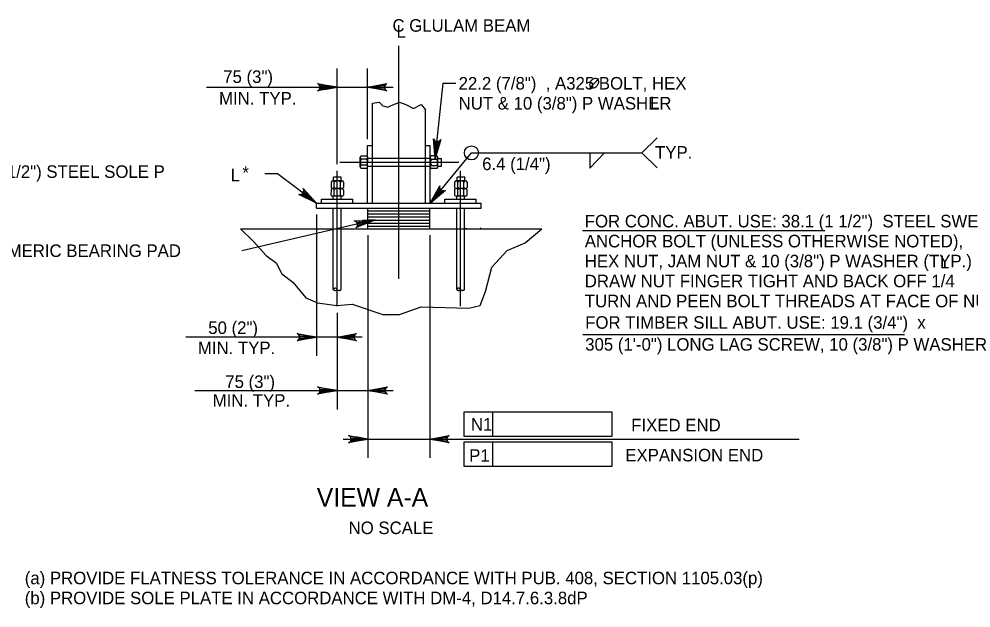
# Model space of a CAD drawing. Extents: x 638263 to 640360, y 293683 to 298655.
# Drawn here: x 638729.9 to 638957.6, y 295056.6 to 295197.6 of the extents above; entities that cross this region are included whole.
import ezdxf

# ---------------------------------------------------------------- set-up
doc = ezdxf.new("R2010")
doc.units = 0
doc.layers.add('3', color=7, linetype='Continuous')
doc.layers.add('4', color=7, linetype='Continuous')

msp = doc.modelspace()

# ---------------------------------------------------------------- linework, layer by layer
at = {"layer": '3'}
for p, q in [((638820.73, 295135.39), (638820.73, 295191.14)), ((638814.39, 295153.48), (638814.39, 295177.4)), ((638827.06, 295153.48), (638827.06, 295175.87)), ((638813.21, 295167.26), (638814.39, 295167.26)), ((638813.21, 295153.48), (638813.21, 295167.26)), ((638827.06, 295167.26), (638828.24, 295167.26)), ((638828.24, 295153.48), (638828.24, 295167.26)), ((638811.72, 295164.84), (638813, 295164.84)), ((638829.79, 295164.79), (638828.5, 295164.79)), ((638806.6, 295163.33), (638835.04, 295163.33)), ((638811.44, 295162.19), (638811.45, 295164.47)), ((638813, 295164.06), (638811.71, 295164.06)), ((638812.99, 295162.56), (638811.71, 295162.56)), ((638813.26, 295162.18), (638813.27, 295164.46)), ((638813.26, 295162.38), (638828.23, 295162.38)), ((638813.27, 295164.25), (638828.24, 295164.25)), ((638828.23, 295162.15), (638828.24, 295164.42)), ((638828.5, 295164.02), (638829.79, 295164.02)), ((638828.5, 295162.52), (638829.79, 295162.52)), ((638830.05, 295162.14), (638830.05, 295164.42)), ((638830.05, 295164.19), (638830.96, 295164.18)), ((638830.05, 295162.34), (638830.95, 295162.34)), ((638830.95, 295162.34), (638830.96, 295164.18)), ((638805.96, 295128.82), (638805.96, 295161.26)), ((638811.71, 295161.84), (638812.99, 295161.84)), ((638829.78, 295161.79), (638828.5, 295161.8)), ((638835.49, 295128.82), (638835.49, 295161.26)), ((638804.5, 295158.54), (638804.5, 295157.26)), ((638807.15, 295158.8), (638804.88, 295158.81)), ((638805.1, 295158.81), (638805.11, 295159.71)), ((638806.95, 295159.71), (638805.11, 295159.71)), ((638805.28, 295157.26), (638805.28, 295158.54)), ((638806.77, 295157.25), (638806.78, 295158.54)), ((638806.95, 295158.8), (638806.95, 295159.71)), ((638807.5, 295158.54), (638807.5, 295157.25)), ((638834.03, 295158.54), (638834.03, 295157.26)), ((638836.68, 295158.8), (638834.4, 295158.81)), ((638836.48, 295159.71), (638834.63, 295159.71)), ((638834.63, 295158.81), (638834.63, 295159.71)), ((638834.8, 295157.26), (638834.8, 295158.54)), ((638836.3, 295157.25), (638836.3, 295158.54)), ((638836.48, 295158.8), (638836.48, 295159.71)), ((638837.03, 295158.54), (638837.03, 295157.25)), ((638804.5, 295156.73), (638804.49, 295155.44)), ((638807.15, 295156.99), (638804.87, 295156.99)), ((638805.27, 295155.44), (638805.27, 295156.73)), ((638806.77, 295155.44), (638806.77, 295156.72)), ((638807.5, 295156.72), (638807.49, 295155.44)), ((638834.03, 295156.73), (638834.02, 295155.44)), ((638836.68, 295156.99), (638834.4, 295156.99)), ((638834.8, 295155.44), (638834.8, 295156.73)), ((638836.3, 295155.44), (638836.3, 295156.72)), ((638837.02, 295156.72), (638837.02, 295155.44)), ((638801.04, 295152.3), (638801.04, 295153.48)), ((638801.04, 295153.48), (638840.41, 295153.48)), ((638802.22, 295153.48), (638802.22, 295154.47)), ((638802.22, 295154.47), (638809.7, 295154.47)), ((638807.14, 295155.17), (638804.87, 295155.18)), ((638805.04, 295154.47), (638805.04, 295155.18)), ((638806.91, 295154.47), (638806.91, 295155.17)), ((638809.7, 295153.48), (638809.7, 295154.47)), ((638831.75, 295154.47), (638839.23, 295154.47)), ((638831.75, 295153.48), (638831.75, 295154.47)), ((638836.67, 295155.17), (638834.4, 295155.18)), ((638834.57, 295154.47), (638834.57, 295155.18)), ((638836.43, 295154.47), (638836.43, 295155.17)), ((638839.23, 295153.48), (638839.23, 295154.47)), ((638840.41, 295152.3), (638840.41, 295153.48)), ((638801.04, 295152.3), (638840.41, 295152.3)), ((638805.04, 295147.38), (638805.04, 295152.3)), ((638806.91, 295147.38), (638806.91, 295152.3)), ((638813.34, 295147.38), (638813.34, 295152.3)), ((638813.34, 295151.67), (638820.73, 295151.67)), ((638813.34, 295150.93), (638820.73, 295150.93)), ((638820.73, 295151.67), (638828.11, 295151.67)), ((638820.73, 295150.93), (638828.11, 295150.93)), ((638828.11, 295147.38), (638828.11, 295152.3)), ((638834.57, 295147.38), (638834.57, 295152.3)), ((638836.43, 295147.38), (638836.43, 295152.3)), ((638813.34, 295150.19), (638820.73, 295150.19)), ((638813.34, 295149.46), (638820.73, 295149.46)), ((638813.34, 295148.72), (638820.73, 295148.72)), ((638820.73, 295150.19), (638828.11, 295150.19)), ((638820.73, 295149.46), (638828.11, 295149.46)), ((638820.73, 295148.72), (638828.11, 295148.72)), ((638782.88, 295147.38), (638854.89, 295147.38)), ((638805.04, 295132.86), (638805.04, 295147.38)), ((638806.91, 295132.85), (638806.91, 295147.38)), ((638813.34, 295147.98), (638820.73, 295147.98)), ((638820.73, 295147.98), (638828.11, 295147.98)), ((638834.57, 295132.86), (638834.57, 295147.38)), ((638836.43, 295132.85), (638836.43, 295147.38))]:
    msp.add_line(p, q, dxfattribs=at)
for points in [[(638814.39, 295177.4), (638815.98, 295177.71), (638816.9, 295176.79), (638818.12, 295176.48), (638818.73, 295176.79), (638820.88, 295177.71), (638822.41, 295177.1), (638824.25, 295176.18), (638826.09, 295177.1), (638827.06, 295175.87)], [(638801.04, 295153.49), (638796.79, 295155.59), (638797.23, 295155.58), (638797.56, 295155.72), (638797.8, 295155.93), (638797.94, 295156.21), (638797.98, 295156.57), (638797.84, 295156.99), (638801.04, 295153.49), (638797.98, 295156.57), (638797.94, 295156.21), (638801.04, 295153.49), (638797.8, 295155.93), (638797.56, 295155.72), (638801.04, 295153.49), (638797.23, 295155.58)], [(638814.77, 295149.46), (638810.43, 295147.55), (638810.72, 295147.87), (638810.83, 295148.22), (638810.82, 295148.53), (638810.69, 295148.83), (638810.44, 295149.09), (638810.03, 295149.25), (638814.77, 295149.46), (638810.44, 295149.09), (638810.69, 295148.83), (638814.77, 295149.46), (638810.82, 295148.53), (638810.83, 295148.22), (638814.77, 295149.46), (638810.72, 295147.87)], [(638782.88, 295147.38), (638785.94, 295144.32), (638789.01, 295140.95), (638791.46, 295139.11), (638792.69, 295136.66), (638795.44, 295134.52), (638798.51, 295130.84), (638801.27, 295129.62), (638805.86, 295129), (638809.54, 295129.31), (638816.9, 295126.86), (638820.88, 295126.86), (638826.09, 295128.7), (638837.43, 295128.39), (638840.19, 295129), (638841.41, 295132.37), (638842.94, 295138.19), (638846.62, 295142.17), (638850.91, 295144.01), (638854.89, 295147.38)]]:
    msp.add_lwpolyline(points, dxfattribs=at)
for centre, radius, start, end in [((638811.87, 295164.45), 0.417, 111.1104, 181.6506), ((638812.85, 295164.45), 0.417, 357.9964, 68.5366), ((638828.65, 295164.41), 0.417, 111.1685, 181.7086), ((638829.64, 295164.4), 0.417, 358.0545, 68.5946), ((638811.82, 295162.2), 0.379, 107.2753, 252.3717), ((638811.87, 295164.45), 0.417, 181.6506, 248.5366), ((638812.64, 295163.31), 1.19, 140.8735, 218.7735), ((638812.07, 295163.31), 1.19, 320.8735, 38.7735), ((638812.88, 295162.2), 0.379, 287.2753, 72.3717), ((638812.85, 295164.45), 0.417, 291.1104, 357.9964), ((638829.43, 295163.27), 1.19, 140.9315, 218.8315), ((638828.61, 295162.16), 0.379, 107.3333, 252.4297), ((638828.65, 295164.41), 0.417, 181.7086, 248.5946), ((638828.86, 295163.27), 1.19, 320.9315, 38.8315), ((638829.67, 295162.16), 0.379, 287.3333, 72.4297), ((638829.64, 295164.4), 0.417, 291.1685, 358.0545), ((638804.89, 295158.39), 0.417, 88.0545, 158.5946), ((638804.89, 295158.39), 0.417, 21.1685, 88.0545), ((638806.02, 295157.61), 1.19, 50.9315, 128.8315), ((638807.14, 295158.43), 0.379, 17.3333, 162.4297), ((638834.42, 295158.39), 0.417, 88.0545, 158.5946), ((638834.42, 295158.39), 0.417, 21.1685, 88.0545), ((638835.55, 295157.61), 1.19, 50.9315, 128.8315), ((638836.66, 295158.43), 0.379, 17.3333, 162.4297), ((638804.88, 295155.59), 0.417, 201.1685, 271.7086), ((638804.89, 295157.41), 0.417, 201.1685, 271.7086), ((638804.88, 295156.58), 0.417, 88.0545, 158.5946), ((638804.88, 295155.59), 0.417, 271.7086, 338.5946), ((638804.88, 295156.58), 0.417, 21.1685, 88.0545), ((638806.03, 295158.18), 1.19, 230.9315, 308.8315), ((638806.02, 295155.8), 1.19, 50.9315, 128.8315), ((638806.02, 295156.37), 1.19, 230.9315, 308.8315), ((638807.13, 295157.37), 0.379, 197.3333, 342.4297), ((638807.13, 295156.61), 0.379, 17.3333, 162.4297), ((638807.13, 295155.55), 0.379, 197.3333, 342.4297), ((638834.41, 295156.58), 0.417, 88.0545, 158.5946), ((638834.41, 295155.59), 0.417, 201.1685, 271.7086), ((638834.41, 295157.41), 0.417, 201.1685, 271.7086), ((638834.41, 295155.59), 0.417, 271.7086, 338.5946), ((638834.41, 295157.41), 0.417, 271.7086, 338.5946), ((638834.41, 295156.58), 0.417, 21.1685, 88.0545), ((638835.55, 295158.18), 1.19, 230.9315, 308.8315), ((638835.55, 295155.8), 1.19, 50.9315, 128.8315), ((638835.55, 295156.37), 1.19, 230.9315, 308.8315), ((638836.66, 295157.37), 0.379, 197.3333, 342.4297), ((638836.66, 295156.61), 0.379, 17.3333, 162.4297), ((638836.66, 295155.55), 0.379, 197.3333, 342.4297), ((638805.17, 295132.86), 0.137, 142.0693, 180), ((638805.17, 295132.86), 0.137, 180, 217.9307), ((638805.33, 295132.74), 0.333, 117.9903, 142.0693), ((638805.33, 295132.98), 0.333, 217.9307, 242.0097), ((638805.43, 295132.54), 0.552, 102.4157, 117.9903), ((638805.43, 295133.17), 0.552, 242.0097, 257.5843), ((638805.5, 295132.24), 0.867, 90, 102.4157), ((638805.5, 295132.24), 0.867, 77.5843, 90), ((638805.57, 295132.54), 0.552, 62.0097, 77.5843), ((638805.57, 295133.17), 0.552, 282.4157, 297.9903), ((638805.67, 295132.74), 0.333, 37.9307, 62.0097), ((638805.67, 295132.98), 0.333, 297.9903, 322.0693), ((638805.82, 295132.86), 0.137, 0, 37.9307), ((638805.82, 295132.86), 0.137, 322.0693, 0), ((638806.1, 295132.85), 0.137, 180, 217.9307), ((638806.25, 295132.97), 0.333, 217.9307, 242.0097), ((638806.36, 295133.16), 0.552, 242.0097, 257.5843), ((638806.49, 295133.16), 0.552, 282.4157, 297.9903), ((638806.59, 295132.97), 0.333, 297.9903, 322.0693), ((638806.75, 295132.85), 0.137, 322.0693, 360), ((638806.75, 295132.85), 0.137, 360, 1.757), ((638834.7, 295132.86), 0.137, 142.0693, 180), ((638834.7, 295132.86), 0.137, 180, 217.9307), ((638834.86, 295132.74), 0.333, 117.9903, 142.0693), ((638834.86, 295132.98), 0.333, 217.9307, 242.0097), ((638834.96, 295132.54), 0.552, 102.4157, 117.9903), ((638834.96, 295133.17), 0.552, 242.0097, 257.5843), ((638835.03, 295132.24), 0.867, 90, 102.4157), ((638835.03, 295132.24), 0.867, 77.5843, 90), ((638835.09, 295132.54), 0.552, 62.0097, 77.5843), ((638835.09, 295133.17), 0.552, 282.4157, 297.9903), ((638835.2, 295132.74), 0.333, 37.9307, 62.0097), ((638835.2, 295132.98), 0.333, 297.9903, 322.0693), ((638835.35, 295132.86), 0.137, 0, 37.9307), ((638835.35, 295132.86), 0.137, 322.0693, 0), ((638835.63, 295132.85), 0.137, 180, 217.9307), ((638835.78, 295132.97), 0.333, 217.9307, 242.0097), ((638835.88, 295133.16), 0.552, 242.0097, 257.5843), ((638836.02, 295133.16), 0.552, 282.4157, 297.9903), ((638836.12, 295132.97), 0.333, 297.9903, 322.0693), ((638836.28, 295132.85), 0.137, 322.0693, 360), ((638836.28, 295132.85), 0.137, 360, 1.757), ((638805.5, 295133.48), 0.867, 257.5843, 270), ((638805.5, 295133.48), 0.867, 270, 282.4157), ((638806.42, 295133.47), 0.867, 257.5843, 270), ((638806.42, 295133.47), 0.867, 270, 282.4157), ((638835.03, 295133.48), 0.867, 257.5843, 270), ((638835.03, 295133.48), 0.867, 270, 282.4157), ((638835.95, 295133.47), 0.867, 257.5843, 270), ((638835.95, 295133.47), 0.867, 270, 282.4157)]:
    msp.add_arc(centre, radius, start, end, dxfattribs=at)
at = {"layer": '4'}
for p, q in [((638805.96, 295162.82), (638805.96, 295185.74)), ((638813.21, 295168.83), (638813.21, 295185.74)), ((638866.29, 295180.91), (638868.53, 295183.37)), ((638774.74, 295181.24), (638819.34, 295181.24)), ((638829.38, 295164.19), (638831.34, 295182.24)), ((638831.34, 295182.24), (638834.34, 295182.24)), ((638878.86, 295165.54), (638882.48, 295169.12)), ((638828.24, 295153.48), (638838.09, 295165.54)), ((638838.09, 295165.54), (638878.86, 295165.54)), ((638866.39, 295165.54), (638866.39, 295161.87)), ((638866.39, 295161.87), (638869.93, 295165.54)), ((638878.86, 295165.54), (638882.48, 295161.97)), ((638791.68, 295160.54), (638788.68, 295160.54)), ((638801.04, 295153.49), (638791.68, 295160.54)), ((638814.77, 295149.46), (638783.19, 295142.11)), ((638801.04, 295150.74), (638801.04, 295116.9)), ((638836.7, 295147.38), (638836.82, 295147.51)), ((638836.82, 295147.5), (638836.95, 295147.38)), ((638840.24, 295147.38), (638840.41, 295147.56)), ((638864.64, 295146.93), (638922.63, 295146.93)), ((638813.34, 295145.82), (638813.34, 295092.51)), ((638828.11, 295145.82), (638828.11, 295092.51)), ((638805.96, 295127.26), (638805.96, 295104.13)), ((638811.93, 295121.4), (638769.8, 295121.4)), ((638864.74, 295122.03), (638941.69, 295122.03)), ((638771.96, 295108.63), (638819.34, 295108.63)), ((638836.38, 295103.52), (638843.22, 295103.52)), ((638836.38, 295097.62), (638836.38, 295103.52)), ((638843.22, 295097.62), (638843.22, 295103.52)), ((638843.22, 295103.52), (638871.68, 295103.52)), ((638871.68, 295103.52), (638871.68, 295097.62)), ((638807.38, 295097.01), (638916.46, 295097.01)), ((638871.68, 295097.62), (638836.38, 295097.62)), ((638836.38, 295096.34), (638843.22, 295096.34)), ((638836.38, 295090.43), (638836.38, 295096.34)), ((638843.22, 295090.43), (638843.22, 295096.34)), ((638843.22, 295096.34), (638871.68, 295096.34)), ((638871.68, 295096.34), (638871.68, 295090.43)), ((638871.68, 295090.43), (638836.38, 295090.43))]:
    msp.add_line(p, q, dxfattribs=at)
for points in [[(638805.96, 295181.24), (638801.3, 295180.36), (638801.66, 295180.61), (638801.85, 295180.92), (638801.9, 295181.24), (638801.85, 295181.55), (638801.66, 295181.86), (638801.3, 295182.11), (638805.96, 295181.24), (638801.66, 295181.86), (638801.85, 295181.55), (638805.96, 295181.24), (638801.9, 295181.24), (638801.85, 295180.92), (638805.96, 295181.24), (638801.66, 295180.61)], [(638813.21, 295181.24), (638817.87, 295182.11), (638817.52, 295181.86), (638817.33, 295181.55), (638817.28, 295181.24), (638817.33, 295180.92), (638817.52, 295180.61), (638817.87, 295180.36), (638813.21, 295181.24), (638817.52, 295180.61), (638817.33, 295180.92), (638813.21, 295181.24), (638817.28, 295181.24), (638817.33, 295181.55), (638813.21, 295181.24), (638817.52, 295181.86)], [(638829.38, 295164.19), (638829.02, 295168.92), (638829.22, 295168.53), (638829.52, 295168.31), (638829.82, 295168.23), (638830.14, 295168.25), (638830.47, 295168.4), (638830.75, 295168.73), (638829.38, 295164.19), (638830.47, 295168.4), (638830.14, 295168.25), (638829.38, 295164.19), (638829.82, 295168.23), (638829.52, 295168.31), (638829.38, 295164.19), (638829.22, 295168.53)], [(638828.24, 295153.48), (638830.51, 295157.65), (638830.48, 295157.21), (638830.6, 295156.87), (638830.81, 295156.63), (638831.08, 295156.47), (638831.44, 295156.42), (638831.86, 295156.54), (638828.24, 295153.48), (638831.44, 295156.42), (638831.08, 295156.47), (638828.24, 295153.48), (638830.81, 295156.63), (638830.6, 295156.87), (638828.24, 295153.48), (638830.48, 295157.21)], [(638801.04, 295121.4), (638796.38, 295120.53), (638796.74, 295120.77), (638796.92, 295121.09), (638796.98, 295121.4), (638796.92, 295121.71), (638796.74, 295122.02), (638796.38, 295122.27), (638801.04, 295121.4), (638796.74, 295122.02), (638796.92, 295121.71), (638801.04, 295121.4), (638796.98, 295121.4), (638796.92, 295121.09), (638801.04, 295121.4), (638796.74, 295120.77)], [(638805.96, 295121.4), (638810.62, 295122.27), (638810.27, 295122.02), (638810.08, 295121.71), (638810.03, 295121.4), (638810.08, 295121.09), (638810.27, 295120.77), (638810.62, 295120.53), (638805.96, 295121.4), (638810.27, 295120.77), (638810.08, 295121.09), (638805.96, 295121.4), (638810.03, 295121.4), (638810.08, 295121.71), (638805.96, 295121.4), (638810.27, 295122.02)], [(638805.96, 295108.63), (638801.3, 295107.76), (638801.66, 295108.01), (638801.85, 295108.32), (638801.9, 295108.63), (638801.85, 295108.95), (638801.66, 295109.26), (638801.3, 295109.51), (638805.96, 295108.63), (638801.66, 295109.26), (638801.85, 295108.95), (638805.96, 295108.63), (638801.9, 295108.63), (638801.85, 295108.32), (638805.96, 295108.63), (638801.66, 295108.01)], [(638813.34, 295108.63), (638818, 295109.51), (638817.65, 295109.26), (638817.46, 295108.95), (638817.41, 295108.63), (638817.46, 295108.32), (638817.65, 295108.01), (638818, 295107.76), (638813.34, 295108.63), (638817.65, 295108.01), (638817.46, 295108.32), (638813.34, 295108.63), (638817.41, 295108.63), (638817.46, 295108.95), (638813.34, 295108.63), (638817.65, 295109.26)], [(638813.34, 295097.01), (638808.68, 295096.13), (638809.04, 295096.38), (638809.23, 295096.69), (638809.28, 295097.01), (638809.23, 295097.32), (638809.04, 295097.63), (638808.68, 295097.88), (638813.34, 295097.01), (638809.04, 295097.63), (638809.23, 295097.32), (638813.34, 295097.01), (638809.28, 295097.01), (638809.23, 295096.69), (638813.34, 295097.01), (638809.04, 295096.38)], [(638828.11, 295097.01), (638832.77, 295097.88), (638832.41, 295097.63), (638832.22, 295097.32), (638832.17, 295097.01), (638832.22, 295096.69), (638832.41, 295096.38), (638832.77, 295096.13), (638828.11, 295097.01), (638832.41, 295096.38), (638832.22, 295096.69), (638828.11, 295097.01), (638832.17, 295097.01), (638832.22, 295097.32), (638828.11, 295097.01), (638832.41, 295097.63)]]:
    msp.add_lwpolyline(points, dxfattribs=at)
for points in [[(638802.96, 295181.74), (638802.96, 295180.74), (638805.96, 295181.24)], [(638816.21, 295181.74), (638816.21, 295180.74), (638813.21, 295181.24)], [(638829.27, 295167.74), (638830.26, 295167.63), (638829.44, 295164.7)], [(638798.95, 295155.69), (638798.34, 295154.89), (638801.04, 295153.48)], [(638830.52, 295155.49), (638829.75, 295156.12), (638828.24, 295153.48)], [(638812, 295149.32), (638812.23, 295148.35), (638815.04, 295149.52)], [(638798.04, 295121.9), (638798.04, 295120.9), (638801.04, 295121.4)], [(638808.96, 295121.9), (638808.96, 295120.9), (638805.96, 295121.4)], [(638802.96, 295109.13), (638802.96, 295108.13), (638805.96, 295108.63)], [(638816.34, 295109.13), (638816.34, 295108.13), (638813.34, 295108.63)], [(638810.34, 295097.51), (638810.34, 295096.51), (638813.34, 295097.01)], [(638831.11, 295097.51), (638831.11, 295096.51), (638828.11, 295097.01)]]:
    msp.add_lwpolyline(points, close=True, dxfattribs=at)
msp.add_circle((638838.09, 295165.54), 1.69, dxfattribs=at)
msp.add_arc((638806.1, 295132.86), 0.137, 180, 182.0078, dxfattribs=at)
msp.add_spline([(638868.3, 295183.12), (638868.12, 295183.26), (638867.95, 295183.31), (638867.73, 295183.33), (638867.6, 295183.33), (638867.39, 295183.28), (638867.19, 295183.19), (638867.05, 295183.11), (638866.79, 295182.9), (638866.58, 295182.63), (638866.45, 295182.38), (638866.38, 295182.15), (638866.36, 295181.93), (638866.38, 295181.75), (638866.47, 295181.48), (638866.57, 295181.35), (638866.76, 295181.2), (638867.05, 295181.13), (638867.38, 295181.14), (638867.8, 295181.33), (638868.1, 295181.59), (638868.33, 295181.91), (638868.48, 295182.24), (638868.53, 295182.61), (638868.47, 295182.85), (638868.31, 295183.12)], degree=3, dxfattribs=at)

# ---------------------------------------------------------------- texts
for s, height, p in [('C GLULAM BEAM', 3, (638819.19, 295194.54)), ('L', 3, (638820.17, 295193.13)), ('75 (3")', 3, (638778.71, 295182.28)), ('22.2 (7/8")  , A325 BOLT, HEX', 3, (638835.02, 295180.7)), ('MIN. TYP.', 3, (638777.72, 295177.1)), ('NUT & 10 (3/8") P WASHER', 3, (638835.02, 295175.91)), ('L', 3, (638880.81, 295176)), ('TYP.', 3, (638882, 295164.15)), ('6.4 (1/4")', 3, (638840.65, 295161.41)), ('12 (1/2") STEEL SOLE P', 3, (638720.05, 295159.55)), ('*', 3, (638783.3, 295159.29)), ('L', 3, (638780.5, 295158.73)), ('FOR CONC. ABUT. USE: 38.1 (1 1/2")  STEEL SWEDGE', 3, (638865.19, 295147.69)), ('ANCHOR BOLT (UNLESS OTHERWISE NOTED), ', 3, (638865.19, 295142.91)), ('ELASTOMERIC BEARING PAD', 3, (638711.31, 295140.61)), ('HEX NUT, JAM NUT & 10 (3/8") P WASHER (TYP.)', 3, (638865.19, 295138.13)), ('L', 3, (638950.17, 295137.91)), ('DRAW NUT FINGER TIGHT AND BACK OFF 1/4', 3, (638865.19, 295133.35)), ('TURN AND PEEN BOLT THREADS AT FACE OF NUTS.', 3, (638865.19, 295128.57)), ('FOR TIMBER SILL ABUT. USE: 19.1 (3/4")  x ', 3, (638865.29, 295123.43)), ('50 (2")', 3, (638775.13, 295122.17)), ('305 (1\'-0") LONG LAG SCREW, 10 (3/8") P WASHER', 3, (638865.29, 295118.18)), ('MIN. TYP.', 3, (638772.65, 295117.35)), ('75 (3")', 3, (638779.2, 295109.25)), ('MIN. TYP.', 3, (638776.2, 295104.75)), ('N1', 3, (638837.94, 295099.05)), ('FIXED END', 3, (638876.3, 295098.86)), ('P1', 3, (638837.54, 295091.58)), ('EXPANSION END', 3, (638874.89, 295091.67)), ('VIEW A-A', 4.429, (638801.08, 295080.85)), ('NO SCALE', 3, (638808.7, 295074.26)), ('(a) PROVIDE FLATNESS TOLERANCE IN ACCORDANCE WITH PUB. 408, SECTION 1105.03(p)', 3, (638731.24, 295062.25)), ('(b) PROVIDE SOLE PLATE IN ACCORDANCE WITH DM-4, D14.7.6.3.8dP', 3, (638731.24, 295057.47))]:
    msp.add_text(s, height=height, dxfattribs=at).set_placement(p)

doc.saveas('drawing.dxf')
